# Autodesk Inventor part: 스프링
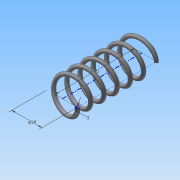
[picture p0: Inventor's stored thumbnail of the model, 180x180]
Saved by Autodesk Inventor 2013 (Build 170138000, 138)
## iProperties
Created: 2016-04
Part Number: 스프링
Material: Generic
Document SubType Name: Modeling
Designer: Administrator
Density: 1 g/cm^3
Mass: -0.00965486 g
Surface Area: 18.9926 cm^2
Volume: -0.00965486 cm^3
Author: Administrator
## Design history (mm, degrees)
sketch "스케치1"
  geometry: L1 (0, 0)-(8, 0); L2 (8, 0)-(8, 42); L3 (8, 42)-(0, 42); L4 (0, 42)-(0, 0); C1 r 1 at (8, 0)
  constraints: 8 end point, 2 parallel, 1 centre point, 1 coincident, 1 horizontal, 1 perpendicular
  dimensions: "d0" = 42 distance of L3.end L1.start (derived); "d1" = 16 diameter of L2 L4; "d2" = 2 diameter of C1
feature "코일1" sketch "스케치1" pitch "d3" = 10; turns "d5" = 6; dims "d4" = 42 (= d0), "d6" = 0, angle "d7" = 90 deg, angle "d8" = 90 deg, "d9" = 0, "d10" = 0
sketch "스케치2"
  geometry: L1 (42, 24.186)-(0, 24.186); L2 (0, 24.186)-(0, -24.186); L3 (0, -24.186)-(42, -24.186); L4 (42, -24.186)-(42, 24.186); 4 further points
  constraints: 8 end point, 3 coincident, 2 midpoint, 2 parallel, 1 horizontal, 1 perpendicular
  dimensions: "d11" = 48.37288 distance of L1.end L2.end
extrude "돌출1" sketch "스케치2" stored distance "d13" = 40; taper "d14" = 0 deg
node "솔리드1"
